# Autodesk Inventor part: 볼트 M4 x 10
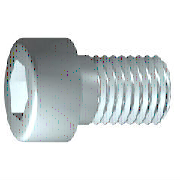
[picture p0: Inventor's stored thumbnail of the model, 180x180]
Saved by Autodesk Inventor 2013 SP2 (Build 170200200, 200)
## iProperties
IsCustomPart: 0
Created: 2016-04
Part Number: 볼트 M4 x 10
Material: 강철, 연강
Description: 6각머리 태핑 나사
Document SubType Name: Modeling
Standard: KS B 1003
Designer: mdu
Standards Organization: KS
Language: ko-KR
Size Designation: M 4 x 10
Categories: <MemberInstance><Categories><Category DisplayName="조임쇠" InternalName="e4da775c-781d-43d5-af7c-5136215cf5a6" Mnemonic="FSTN"><Category DisplayName="볼트" InternalN
Density: 7.86 g/cm^3
Mass: 2.0371 g
Surface Area: 3.0572 cm^2
Volume: 0.259174 cm^3
Author: mdu
Revision Number: 1
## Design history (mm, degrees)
sketch "스케치1"
  geometry: L1 (-1, 0)-(10, 0); L2 (10, 0)-(10, 2); L3 (10, 2)-(1.75, 2); L4 (1.75, 2)-(1.32, 2); L5 (1.32, 2)-(0, 2); L6 (0, 2)-(0, 3.5); L7 (0, 3.5)-(-4, 3.5); L8 (-4, 3.5)-(-4, 1.732); L9 (-4, 1.732)-(-2, 1.732); L10 (-2, 1.732)-(-1, 0); L11 (-6.8, 0)-(12.8, 0) reference; L12 (0, -0.7)-(0, 4.2) reference; L13 (1.75, 2)-(0, 2)
  constraints: 22 end point, 6 parallel, 2 collinear, 2 perpendicular, 1 horizontal, 1 point on line
  dimensions: "d1" = 8.25 distance from line of L3.end L2 (= GEL); "d2" = 0.42952 distance of L4.end L3.end (computed from GAL); "d3" = 4 distance between parallel lines of L8 L6 (= KOH); "d4" = 2 distance of L8.end L9.end (= INTI); "d5" = 60 deg angle of L10 L1; "d6" = 4 diameter of L3 L1 (= GD); "d7" = 4 diameter of L5 L1 (= BDM); "d8" = 3.4641 diameter of L9 L1 (= 1.1547 x SW); "d9" = 7 diameter of L7 L1 (= KOD); "d26" = 10 distance between parallel lines of L12 L2 (= NLG)
revolve "본체" sketch "스케치1" stored, may be unused: angle "d10" = 90 deg
sketch "스케치2"
  geometry: L1 (0, -4.9)-(0, 4.9) reference; L2 (-4.9, 0)-(4.9, 0) reference; L3 (1.732, 0)-(0.866, -1.5); L4 (0.866, -1.5)-(-0.866, -1.5); L5 (-0.866, -1.5)-(-1.732, 0); L6 (-1.732, 0)-(-0.866, 1.5); L7 (-0.866, 1.5)-(0.866, 1.5); L8 (0.866, 1.5)-(1.732, 0); 2 further points
  constraints: 12 end point, 1 coincident, 1 horizontal alignment, 1 point on line, 12 other
extrude "슬롯" join sketch "스케치2" stored distance "d11" = 10; taper "d12" = 0 deg
workplane "Work Plane1"
fillet "Fillet2" dims "d30" = 0.1 (= R)
body "Solid1"
fillet "모깎기1" dims "d17" = 0.4 (= RR)
feature "스레드" dims "d13" = 8.25 (= GEL), "d14" = 0
chamfer "모따기1" distance "d15" = 0.42941 (= -0.5 x SPD + 0.5 x GD); stored, may be unused: second distance "d16" = 0.42941 (= GUL), angle "d27" = 45 deg
other parameters: "GD" = 4 (= NND) [user parameter; used in 2 equation terms], "NLG" = 10 [user parameter; used in 1 equation term], "GEL" = 8.25 [user parameter; used in 2 equation terms], "KOD" = 7 [user parameter; used in 1 equation term], "KOH" = 4 [user parameter; used in 1 equation term], "INTI" = 2 [user parameter; used in 1 equation term], "GAL" = 0.42941 (= 0.61345 x PTC) [user parameter; used in 1 equation term], "GUL" = 0.42941 (= 0.61345 x PTC) [user parameter; used in 1 equation term], "BDM" = 4 (= NND) [user parameter; used in 1 equation term], "SW" = 3 [user parameter; used in 2 equation terms], "RR" = 0.4 [user parameter; used in 1 equation term], "SPD" = 3.14117 (= NND - 1.2269 x PTC) [user parameter; used in 1 equation term], "d19" = 0, "d28" = 0, "d29" = 0, "R" = 0.1 [user parameter; used in 1 equation term], "PHH" = 0.2 [user parameter], "GD1" = 3.14117 (= THREADDIA - 1.2269 x PTC) [user parameter], "THREADDIA" = 4 [user parameter; used in 1 equation term], "FAWI" = 45 deg [user parameter], "TPU" = 14.28571 (computed from PTC) [user parameter], "PTC" = 0.7 [user parameter; used in 5 equation terms], "NND" = 4 [user parameter; used in 3 equation terms], "TOA" = 30 deg [user parameter], "E0" = 3.465 (= 1.155 x SW) [user parameter]
